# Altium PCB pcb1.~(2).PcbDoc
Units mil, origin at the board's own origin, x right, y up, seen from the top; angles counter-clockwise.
Board outline 3620 x 2165 mil, 2 copper layers (Top Layer, Bottom Layer); 65 components, 116 nets, 447 pads, 112 vias.
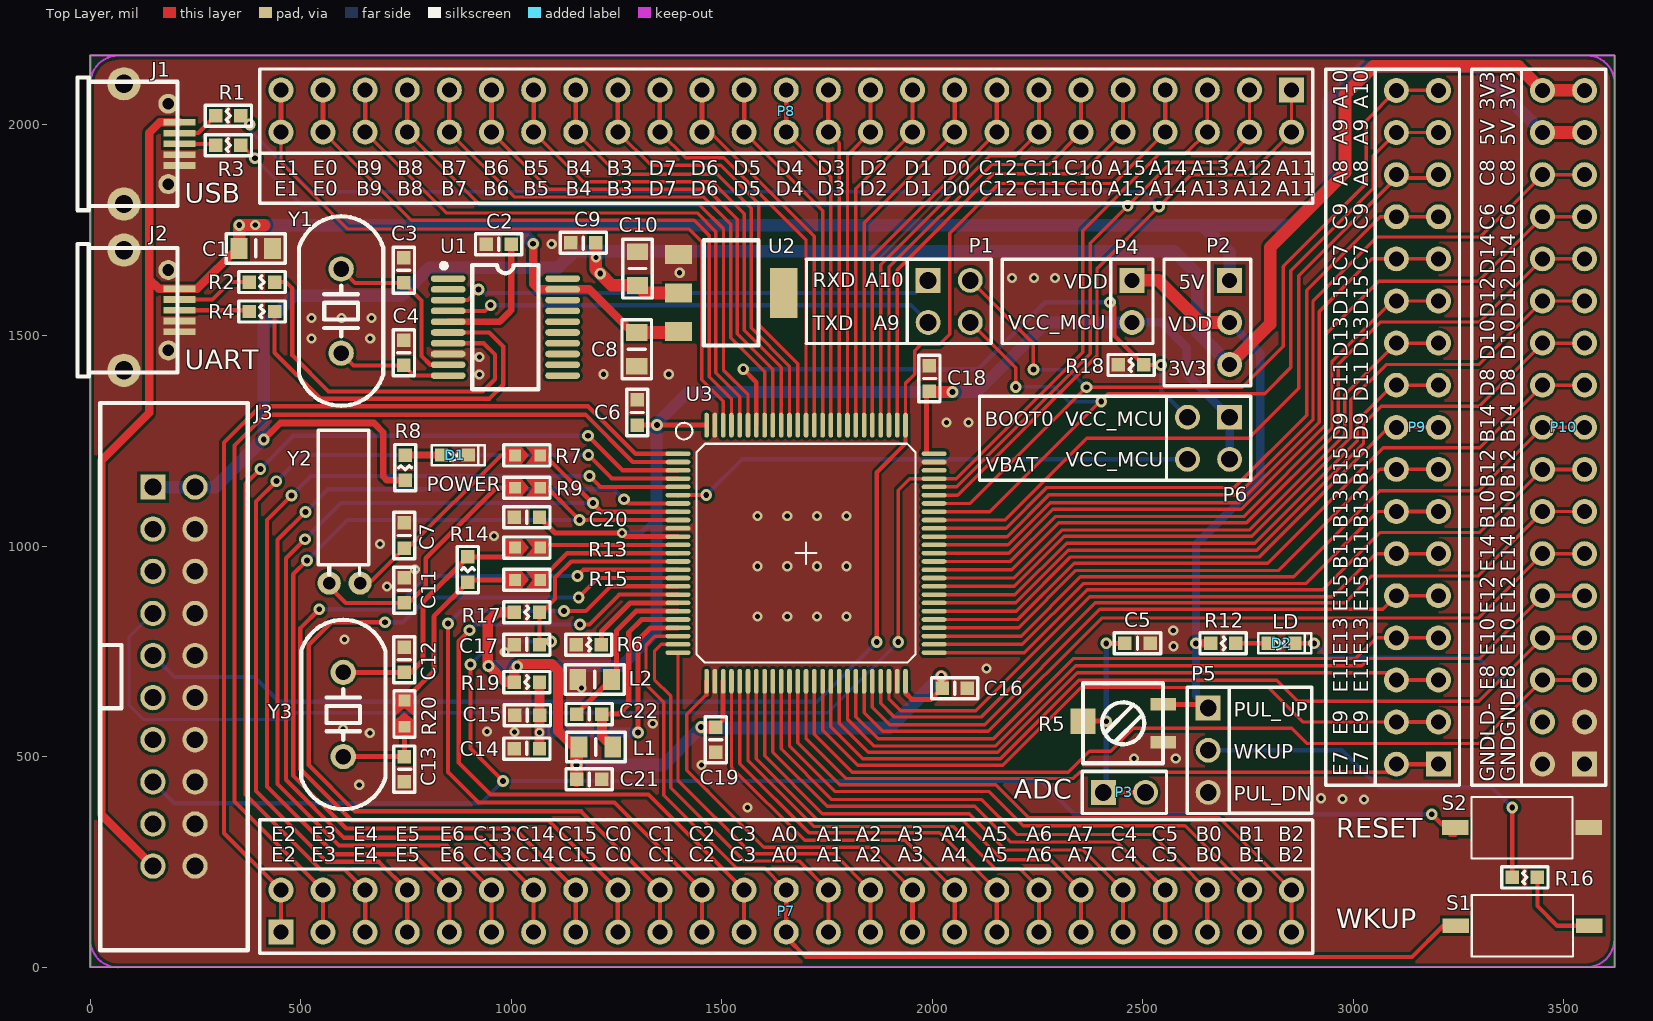
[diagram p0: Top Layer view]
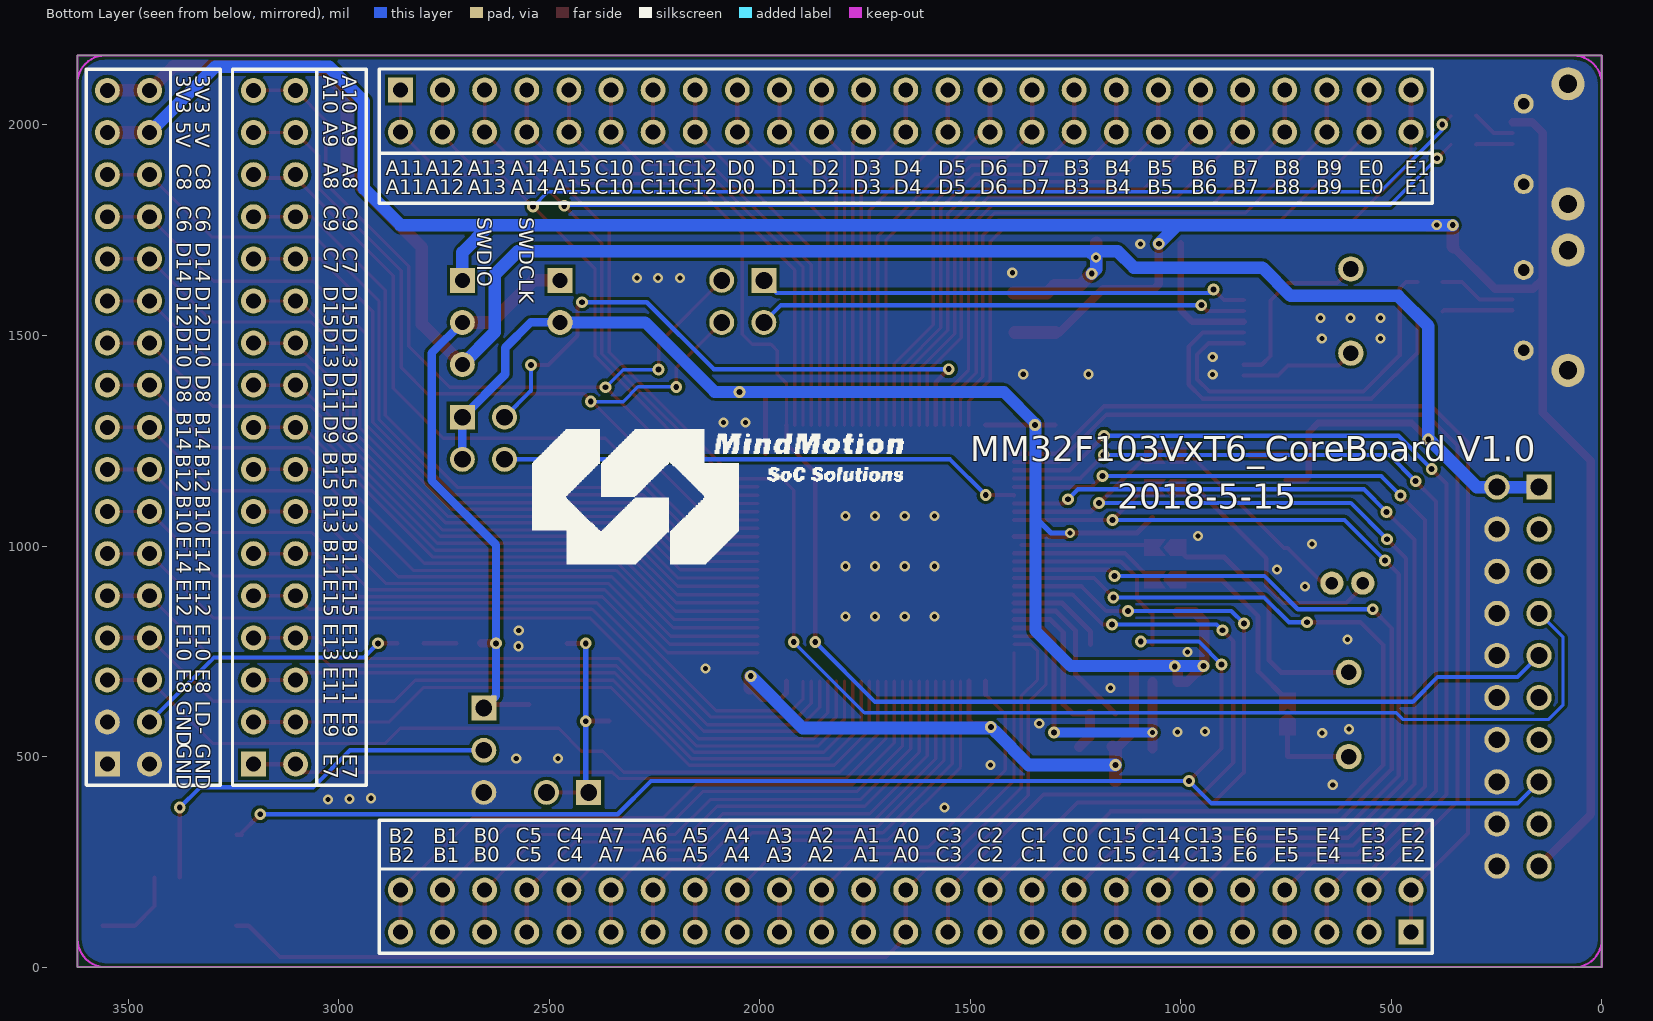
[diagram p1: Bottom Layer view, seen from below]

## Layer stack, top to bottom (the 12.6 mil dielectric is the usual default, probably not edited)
Top Layer: signal copper 1.4
Dielectric: dielectric 12.6, FR-4, Dk 4.8
Bottom Layer: signal copper 1.4

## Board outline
0,0 0,2165 3620,2165 3620,0

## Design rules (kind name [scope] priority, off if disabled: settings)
Clearance [All] p1: gap=7
MinimumSolderMaskSliver [All] p1: minsoldermaskwidth=8
PolygonConnect [All] p1: connectstyle=Direct reliefconductorwidth=10 reliefentries=4 polygonreliefangle="90 Angle"
RoutingVias [All] p1: holewidth=28 width=50 viastyle="Through Hole" minholewidth=14 minwidth=28 maxholewidth=30 maxwidth=50
SilkToSilkClearance [All] p1: silktosilkclearance=0
SilkscreenOverComponentPads [All] p1: minsilkscreentomaskgap=8
SolderMaskExpansion [All] p1: expansion=4
Width [All] p1: maxlimit=50 minlimit=8 preferedwidth=10
25 further rules are at their usual default settings.

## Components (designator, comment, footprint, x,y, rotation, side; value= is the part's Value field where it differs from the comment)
C1 "4.7uF" C-0805 393,1707 r180 top
C2 "104" C-0603 970,1717 r0 top
C3 "22pF" C-0603 745,1655 r270 top
C4 "22pF" C-0603 745,1459 r270 top
C5 "104" C-0603 2487.23,769 r180 top
C6 "104" C-0603 1299,1317 r90 top
C7 "15pF" C-0603 746,1025 r270 top
C8 "4.7uF" C-0805 1298,1467 r90 top
C9 "104" C-0603 1171,1720 r0 top
C10 "10uF" C-0805 1300,1659 r270 top
C11 "15pF" C-0603 746,895 r270 top
C12 "22pF" C-0603 746,730 r270 top
C13 "22pF" C-0603 746,470 r90 top
C14 "1uF" C-0603 1037,519 r180 top
C15 "103" C-0603 1038,598 r180 top
C16 "104" C-0603 2053,662 r180 top
C17 "104" C-0603 1037,765.86 r180 top
C18 "104" C-0603 1993,1398 r90 top
C19 "104" C-0603 1486,540 r270 top
C20 "104" C-0603 1037,1068 r180 top
C21 "1uF" C-0603 1185,446 r0 top
C22 "1uF" C-0603 1185,601 r180 top
D1 "RED" LED-0603 866,1216 r270 top
D2 "BLUE" LED-0603 2829,769 r270 top
J1 "USB_Micro_OX" USB_MICRO_OX_S 206,1955 r90 top
J2 "USB_Micro_OX" USB_MICRO_OX_S 206,1560 r90 top
J3 "CON20A" HEADERBG10X2H 149,1140 r90 top
L1 "Res Semi" C-0805 1201,523 r0 top
L2 "Res Semi" C-0805 1198,682.86 r0 top
P1 "Header 2X2" HDR2X2 1990,1631 r270 top
P2 "Header 3" HDR1X3#1 2706,1631 r270 top
P3 "Header 2" HDR1X2#1 2406,415 r0 top
P4 "Header 2" HDR1X2#2 2474,1631 r270 top
P5 "Header 3" HDR1X3#2 2655,615 r270 top
P6 "Header 2X2" HDR2X2 2706,1305.94 r180 top
P7 "Header 25X2" HDR2X25 453,83 r0 top
P8 "Header 25X2" HDR2X25 2853,2083 r180 top
P9 "Header 17X2" HDR2X17 3202,482 r90 top
P10 "Header 17X2" HDR2X17 3549,482 r90 top
R1 "22R" R-0603 328,2022 r0 top
R2 "22R" R-0603 408,1627 r0 top
R3 "22R" R-0603 328,1952 r0 top
R4 "22R" R-0603 408,1557 r0 top
R5 "10K" R-VR-S 2453,579 r90 top
R6 "0R" R-0603 1184,765.71 r180 top
R7 "NC" NC-0603#1 1009,1216.14 r0 top
R8 "4.7K" R-0603 748,1186 r270 top
R9 "NC" NC-0603#1 1009,1139.29 r0 top
R12 "3K" R-0603 2690.7,769 r180 top
R13 "NC" NC-0603#1 1009,997.43 r0 top
R14 "510K" R-0603 897,944 r270 top
R15 "NC" NC-0603#1 1009,920.57 r0 top
R16 "1K" R-0603 3407,213 r0 top
R17 "47K" R-0603 1037,842.71 r180 top
R18 "4.7K" R-0603 2472,1430 r0 top
R19 "0R" R-0603 1037,677 r180 top
R20 "510R" NC-0603#2 746,575 r90 top
S1 "SW-PB" 3x6x2.5 3281,171 r0 top
S2 "SW-PB" 3x6x2.5 3280,404 r0 top
U1 "CH340T" SSOP-20_208MIL 986,1520 r270 top
U2 "LD1117" SOT223 1522,1601 r270 top
U3 "MM32F103VET6" LQFP100 1700,983 r0 top
Y1 "12M" X'TAL 596,1458 r90 top
Y2 "32.768K" X'TAL-32768 641,912 r180 top
Y3 "8M" X'TAL 601,500 r90 top

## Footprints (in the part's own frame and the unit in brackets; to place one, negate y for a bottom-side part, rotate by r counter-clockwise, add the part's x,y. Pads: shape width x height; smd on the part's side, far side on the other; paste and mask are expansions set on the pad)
3x6x2.5 [mm]
  rect 1.6x0.9 smd: 1(-0.965,-1.85) 2(7.087,-1.85)
  silkscreen extent 0,-3.71 6.1,0
C-0603 [mil]
  rect 32x32 smd: 1(-30,0) 2(30,0)
  silkscreen extent -55,-25 55,25
C-0805 [mil]
  rect 40x50 smd: 1(-40,0) 2(40,0)
  silkscreen extent -70,-35 70,35
HDR1X2#1 [mm] "Connector; Header; 2 Position"
  rect 1.5x1.5 hole 1.016: 1(0,0)
  round 1.5 hole 1.016: 2(2.54,0)
  silkscreen extent -1.27,-1.27 3.81,1.27
HDR1X2#2 [mm] "Connector; Header; 2 Position"
  rect 1.5x1.5 hole 0.9: 1(0,0)
  round 1.5 hole 0.9: 2(2.54,0)
  silkscreen extent -1.27,-1.27 3.81,1.27
HDR1X3#1 [mm] "Connector; Header; 3 Position"
  rect 1.5x1.5 hole 0.9: 1(0,0)
  round 1.5 hole 0.9: 2(2.54,0) 3(5.08,0)
  silkscreen extent -1.27,-1.27 6.35,1.27
HDR1X3#2 [mm] "Connector; Header; 3 Position"
  rect 1.5x1.5 hole 1.016: 1(0,0)
  round 1.5 hole 1.016: 2(2.54,0) 3(5.08,0)
  silkscreen extent -1.27,-1.27 6.35,1.27
HDR2X2 [mm] "Connector; Header; 2x2 Position"
  rect 1.5x1.5 hole 1.016: 1(0,0)
  round 1.5 hole 1.016: 2(0,2.54) 3(2.54,0) 4(2.54,2.54)
  silkscreen extent -1.27,-1.27 3.81,3.81
HDR2X17 [mm] "Connector; Header; 17x2 Position"
  rect 1.5x1.5 hole 0.9: 1(0,0)
  round 1.5 hole 0.9: 2(0,2.54) 3(2.54,0) 4(2.54,2.54) 5(5.08,0) 6(5.08,2.54) 7(7.62,0) 8(7.62,2.54) 9(10.16,0) 10(10.16,2.54) 11(12.7,0) 12(12.7,2.54) 13(15.24,0) 14(15.24,2.54) 15(17.78,0) 16(17.78,2.54) 17(20.32,0) 18(20.32,2.54) 19(22.86,0) 20(22.86,2.54) 21(25.4,0) 22(25.4,2.54) 23(27.94,0) 24(27.94,2.54) 25(30.48,0) 26(30.48,2.54) 27(33.02,0) 28(33.02,2.54) 29(35.56,0) 30(35.56,2.54) 31(38.1,0) 32(38.1,2.54) 33(40.64,0) 34(40.64,2.54)
  silkscreen extent -1.27,-1.27 41.91,3.81
HDR2X25 [mm] "Connector; Header; 25x2 Position"
  rect 1.5x1.5 hole 0.9: 1(0,0)
  round 1.5 hole 0.9: 2(0,2.54) 3(2.54,0) 4(2.54,2.54) 5(5.08,0) 6(5.08,2.54) 7(7.62,0) 8(7.62,2.54) 9(10.16,0) 10(10.16,2.54) 11(12.7,0) 12(12.7,2.54) 13(15.24,0) 14(15.24,2.54) 15(17.78,0) 16(17.78,2.54) 17(20.32,0) 18(20.32,2.54) 19(22.86,0) 20(22.86,2.54) 21(25.4,0) 22(25.4,2.54) 23(27.94,0) 24(27.94,2.54) 25(30.48,0) 26(30.48,2.54) 27(33.02,0) 28(33.02,2.54) 29(35.56,0) 30(35.56,2.54) 31(38.1,0) 32(38.1,2.54) 33(40.64,0) 34(40.64,2.54) 35(43.18,0) 36(43.18,2.54) 37(45.72,0) 38(45.72,2.54) 39(48.26,0) 40(48.26,2.54) 41(50.8,0) 42(50.8,2.54) 43(53.34,0) 44(53.34,2.54) 45(55.88,0) 46(55.88,2.54) 47(58.42,0) 48(58.42,2.54) 49(60.96,0) 50(60.96,2.54)
  silkscreen extent -1.27,-1.27 62.23,3.81
HEADERBG10X2H [mil]
  rect 60x60 hole 40: 1(0,0)
  round 60 hole 40: 2(0,-100) 3(-100,0) 4(-100,-100) 5(-200,0) 6(-200,-100) 7(-300,0) 8(-300,-100) 9(-400,0) 10(-400,-100) 11(-500,0) 12(-500,-100) 13(-600,0) 14(-600,-100) 15(-700,0) 16(-700,-100) 17(-800,0) 18(-800,-100) 19(-900,0) 20(-900,-100)
  silkscreen extent -1100,-225 200,125
LED-0603 [mm]
  rect 0.8x0.8 smd: 1(0,-0.8) 2(0,0.8)
  silkscreen extent -0.6,-1.4 0.6,1.8
LQFP100 [mm]
  oval 1.5x0.279 smd: 1(-7.725,6) 2(-7.725,5.5) 3(-7.725,5) 4(-7.725,4.5) 5(-7.725,4) 6(-7.725,3.5) 7(-7.725,3) 8(-7.725,2.5) 9(-7.725,2) 10(-7.725,1.5) 11(-7.725,1) 12(-7.725,0.5) 13(-7.725,0) 14(-7.725,-0.5) 15(-7.725,-1) 16(-7.725,-1.5) 17(-7.725,-2) 18(-7.725,-2.5) 19(-7.725,-3) 20(-7.725,-3.5) 21(-7.725,-4) 22(-7.725,-4.5) 23(-7.725,-5) 24(-7.725,-5.5) 25(-7.725,-6) 51(7.725,-6) 52(7.725,-5.5) 53(7.725,-5) 54(7.725,-4.5) 55(7.725,-4) 56(7.725,-3.5) 57(7.725,-3) 58(7.725,-2.5) 59(7.725,-2) 60(7.725,-1.5) 61(7.725,-1) 62(7.725,-0.5) 63(7.725,0) 64(7.725,0.5) 65(7.725,1) 66(7.725,1.5) 67(7.725,2) 68(7.725,2.5) 69(7.725,3) 70(7.725,3.5) 71(7.725,4) 72(7.725,4.5) 73(7.725,5) 74(7.725,5.5) 75(7.725,6)
  oval 0.279x1.5 smd: 26(-6,-7.725) 27(-5.5,-7.725) 28(-5,-7.725) 29(-4.5,-7.725) 30(-4,-7.725) 31(-3.5,-7.725) 32(-3,-7.725) 33(-2.5,-7.725) 34(-2,-7.725) 35(-1.5,-7.725) 36(-1,-7.725) 37(-0.5,-7.725) 38(0,-7.725) 39(0.5,-7.725) 40(1,-7.725) 41(1.5,-7.725) 42(2,-7.725) 43(2.5,-7.725) 44(3,-7.725) 45(3.5,-7.725) 46(4,-7.725) 47(4.5,-7.725) 48(5,-7.725) 49(5.5,-7.725) 50(6,-7.725) 76(6,7.725) 77(5.5,7.725) 78(5,7.725) 79(4.5,7.725) 80(4,7.725) 81(3.5,7.725) 82(3,7.725) 83(2.5,7.725) 84(2,7.725) 85(1.5,7.725) 86(1,7.725) 87(0.5,7.725) 88(0,7.725) 89(-0.5,7.725) 90(-1,7.725) 91(-1.5,7.725) 92(-2,7.725) 93(-2.5,7.725) 94(-3,7.725) 95(-3.5,7.725) 96(-4,7.725) 97(-4.5,7.725) 98(-5,7.725) 99(-5.5,7.725) 100(-6,7.725)
  silkscreen extent -7.86,-6.6 6.6,7.87
NC-0603#1 [mil]
  rect 28x28 smd: 1(0,-1) 2(60,-1)
  Top Layer region: -22,-21 16,-21 32,-1 16,19 -22,19
  Top Layer region: 26,19 42,-1 26,-21 78,-21 78,19
  silkscreen extent -27,-26 83,24
NC-0603#2 [mil]
  rect 28x28 smd: 1(-4,-0.33) 2(58,-0.33)
  Top Layer region: -24,-20.33 14,-20.33 30,-0.33 14,19.67 -24,19.67
  Top Layer region: 24,19.67 40,-0.33 24,-20.33 76,-20.33 76,19.67
  silkscreen extent -29,-25 81,25
R-0603 [mil]
  rect 32x32 smd: 1(-30,0) 2(30,0)
  silkscreen extent -55,-25 55,25
R-VR-S [mil]
  rect 30x60 smd: 1(-45,-95) 3(45,-95)
  rect 60x60 smd: 2(5,95)
  silkscreen extent -95,-95 95,95
SOT223 [mil]
  rect 45x65 smd: 1(-91,-125) 2(0,-125) 3(91,-125)
  rect 118x65 smd: 4(0,125)
  silkscreen extent -125,-65 125,65
SSOP-20_208MIL [mm]
  oval 0.4x2.1 smd mask+0.051: 1(-2.925,-3.45) 2(-2.275,-3.45) 3(-1.625,-3.45) 4(-0.975,-3.45) 5(-0.325,-3.45) 6(0.325,-3.45) 7(0.975,-3.45) 8(1.625,-3.45) 9(2.275,-3.45) 10(2.925,-3.45) 11(2.925,3.45) 12(2.275,3.45) 13(1.625,3.45) 14(0.975,3.45) 15(0.325,3.45) 16(-0.325,3.45) 17(-0.975,3.45) 18(-1.625,3.45) 19(-2.275,3.45) 20(-2.925,3.45)
  silkscreen extent -3.85,-3.86 3.75,2
USB_MICRO_OX_S [mm]
  rect 0.4x1.905 smd: 1(1.3,-0.153) 2(0.65,-0.153) 3(0,-0.153) 4(-0.65,-0.153) 5(-1.3,-0.153)
  round 1.2 hole 0.7: 6(2.425,0.52) 7(-2.425,0.52)
  round 2 hole 1.1: 8(-3.625,3.2) 9(3.625,3.2)
  silkscreen extent -4,-0.04 4,6
X'TAL [mil]
  round 60 hole 37: 1(0,0) 2(200,0)
  silkscreen extent -125,-100 325,100
X'TAL-32768 [mil]
  round 55 hole 30: 1(73.35,0) 2(0,0)
  silkscreen extent -21,-363 99,-20

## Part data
C1 C2 C3 C4 C5 C6 C7 C8 C9 C10 C11 C12 C13 C14 C15 C16 C18 C19 C20 C21 C22: library part CAP, "Capacitor"
C17: library part Cap, "Capacitor"
D1 D2: library part LED0, "Typical INFRARED GaAs LED"
L1 L2: "Semiconductor Resistor"
P1 P6: "Header, 2-Pin, Dual row"
P2 P5: "Header, 3-Pin"
P3 P4: "Header, 2-Pin"
P7 P8: "Header, 25-Pin, Dual row"
P9 P10: "Header, 17-Pin, Dual row"
R1 R2 R3 R4 R6 R7 R8 R9 R12 R13 R15 R16 R17 R18 R19 R20: library part Res2, "Resistor"
R5: library part "RESISTOR VAR"
R14: library part RES
S1 S2: "Switch"
U2: library part LD1117/SOT_0
U3: library part LQFP100
Y1 Y2 Y3: library part XTAL, "Crystal Oscillator"

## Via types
v1: diameter 28, hole 14, Top Layer to Bottom Layer, 57 vias
v2: diameter 24, hole 12, Top Layer to Bottom Layer, 55 vias

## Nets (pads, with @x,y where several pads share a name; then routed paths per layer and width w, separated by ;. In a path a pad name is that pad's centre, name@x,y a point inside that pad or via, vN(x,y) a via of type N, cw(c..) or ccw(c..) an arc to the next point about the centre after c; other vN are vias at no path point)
3V3: C9.2 C10.2 J3.1 J3.2 P2.3 P10.33 P10.34 R8.2 U2.2 | length 5330.4
  Top Layer w16: v1(412.19,1252.81) 451.37,1292 674,1292 696,1270 696,1165 705,1156 R8.2
  Top Layer w30: v2@1201,1683 1201,1657 v1(1211.24,1646.76) 1239,1619 C10.2 1318,1601 U2.2 ; v2(1201,1685) C9.2 ; P2.3 2802,1527 2802,1709 2980,1887 2980,2072 3047,2139 3392,2139 P10.34 P10.33
  Bottom Layer w30: J3.1 J3.2 297,1140 v1@409.81,1252.81 ; v1(1211.24,1646.76) 1201,1657 v2(1201,1685) 1216,1700 ; P2.3 2629,1508 2629,1645 2574,1700 1216,1700 ; v1@409.81,1252.81 v1@412.19,1255.19 ; v1@409.81,1252.81 v1(412.19,1252.81) v1@412.19,1255.19 ; v1@412.19,1255.19 412.19,1522.19 484,1594 739,1594 806,1661 1111,1661 1150,1700 1216,1700
+5V: C1.2 C8.2 J1.1 J2.1 J3.19 P2.1 P10.31 P10.32 U1.19 U2.3 | length 6551.2
  Top Layer w20: J3.19 26,363 26,1202 140,1316 140,1634 ; J1.1 165,2006.18 140,1981.18 140,1646 140,1634 ; C1.2@353,1710 254.18,1611.18 J2.1 162.82,1611.18 140,1634 ; v1(1052,1718) 1052,1622 1064.43,1609.57 U1.19 1185.43,1609.57 1288,1507 C8.2 ; U2.3@1394,1507 U2.3
  Top Layer w30: C1.2@353,1710 354,1711 v1(354,1762) v2(392,1762) 413,1762 ; C8.2 U2.3@1394,1507 ; P10.32 P10.31
  Bottom Layer w30: v1(354,1762) v2(392,1762) 983,1762 1008,1762 ; 1016,1762 1008,1762 ; v1(1052,1718) 1008,1762 ; P2.1 2706,1697 2641,1762 ; P10.32 3293,2138 3022,2138 2940,2056 2940,1849 2853,1762 2641,1762 ; 1008,1762 2616,1762 2641,1762
BOOT0: P6.3 R18.2 U3.94 | length 1455.8
  Top Layer w10: v1(1551,1420) 1581.89,1389.11 U3.94 ; v1(2422,1579) 2432.47,1568.53 2432.47,1499.53 R18.2 v1(2543,1430)
  Bottom Layer w10: v1(1551,1420) 2109,1420 2268,1579 v1(2422,1579) ; v1(2543,1430) 2543,1368.94 P6.3
CH340_DN: R2.2 U1.7 | length 916.7
  Top Layer w10: R2.2 465,1627 480,1612 480,1453 566,1367 932,1367 961,1396 961,1455 934.39,1481.61 U1.7
CH340_DP: R4.2 U1.6 | length 935.4
  Top Layer w10: R4.2 438,1459 547,1350 948,1350 981,1383 981,1474 947.8,1507.2 U1.6
GND: C1.1 C2.1 C3.1 C4.1 C5.1 C6.2 C7.1 C8.1 C9.1 C10.1 C11.1 C12.1 C13.1 C14.2 C15.2 C16.1 C17.2 C18.2 C19.2 C20.2 C21.2 D1.2 J1.4 J1.5 J1.6 J1.7 J1.8 J1.9 J2.4 J2.5 J2.6 J2.7 J2.8 J2.9 J3.4 J3.6 J3.8 J3.10 J3.12 J3.14 J3.16 J3.18 J3.20 L2.1 P5.3 P10.1 P10.2 P10.3 R5.1 R6.2 R18.1 S2.2 U1.8 U2.1 U3.10 U3.27 U3.49 U3.74 U3.99
  other v2: 1561,379 3025,398 2974,399 2923,401 639,433 1452,480 2479,495 2578,495 664,556 1008,558 942,560 600,565 1336,579 1167,663 2129,709 984,748 2573,762 604,778 2572,799 1585,833 1655.33,833 1725.67,833 1796,833 705,904 771,944 1585,952 1655.33,952 1725.67,952 1796,952 688,1005 959,1024 1585,1071 1655.33,1071 1725.67,1071 1796,1071 2034,1293 2086,1293 924,1407 1219,1408 1374,1408 924,1449 526,1493 665,1493 526,1542 597,1542 668,1542 2189,1637 2241,1637 2291,1637 1400,1649 1096,1717
LD-: D2.2 P10.4 | length 666
  Top Layer w10: D2.2 v1(2906,769)
  Bottom Layer w10: v1(2906,769) 2940,735 3296,735 P10.4
NetC3_2: C3.2 U1.9 Y1.2 | length 425.8
  Top Layer w10: Y1.2 629,1625 C3.2 787,1583 787,1451 807.57,1430.43 U1.9
NetC4_2: C4.2 U1.10 Y1.1 | length 276.2
  Top Layer w10: Y1.1 625,1429 C4.2 769.16,1404.84 U1.10
NetC5_2: C5.2 P3.1 P3.2 R5.2 | length 546.2
  Top Layer w10: P3.1 P3.2
  Top Layer w12: R5.2 v1(2413,584) ; v1(2413,769) C5.2
  Bottom Layer w12: P3.1@2413,422 v1(2413,769)
NetC7_2: C7.2 R7.1 Y2.2 | length 520.4
  Top Layer w10: Y2.2 663,912 C7.2 755,995 975.14,1215.14 R7.1 982.14,1215.14
NetC11_2: C11.2 R9.1 Y2.1 | length 630.2
  Top Layer w10: Y2.1@567.65,891.35 Y2.1 ; Y2.1@567.65,904.35 607,865 C11.2 757,865 797,905 797,971 964.29,1138.29 R9.1
NetC12_2: C12.2 R13.1 R14.1 Y3.2 | length 612.2
  Top Layer w12: Y3.2 C12.2 762,700 790,728 790,867 R14.1 986.57,974 R13.1
NetC13_2: C13.2 R20.1 Y3.1 | length 216.1
  Top Layer w12: Y3.1 C13.2 746,570.67 R20.1
NetC14_1: C14.1 C15.1 R19.1 U3.22 | length 718.2
  Top Layer w12: v1(1301,557) 1301,776 1330.83,805.83 U3.22
  Top Layer w24: C14.1 R19.1
  Bottom Layer w24: v2(1067,557) v1(1301,557)
NetD1_1: D1.1 R8.1 | length 86.5
  Top Layer w16: R8.1 D1.1
NetD2_1: D2.1 R12.1 | length 76.8
  Top Layer w10: R12.1 D2.1
NetJ2_2: J2.2 R2.1 | length 183.1
  Top Layer w10: J2.2 290.59,1585.59 332,1627 R2.1
NetJ2_3: J2.3 R4.1 | length 167.2
  Top Layer w10: J2.3 375,1560 R4.1
NetP1_1: P1.1 U1.3 | length 1165.9
  Top Layer w10: U1.3 896.98,1583.98 v1(922,1609)
  Bottom Layer w10: v1(922,1609) 930,1601 1960,1601 P1.1
NetP1_3: P1.3 U1.4 | length 1162.4
  Top Layer w10: U1.4 937.39,1558.39 v1(951,1572)
  Bottom Layer w10: v1(951,1572) 1949,1572 P1.3
NetP5_2: P5.2 R16.1 | length 944.3
  Top Layer w10: R16.1 v1(3377,379)
  Bottom Layer w10: P5.2 2973,515 3061,427 3329,427 v1(3377,379)
NetR6_1: R6.1 U3.19 | length 240.3
  Top Layer w12: R6.1@1214,766.71 1214,797 1281.89,864.89 U3.19
NetR13_2: R13.2 U3.12 | length 311.5
  Top Layer w10: R13.2 1075.26,1002.68 U3.12@1377.87,1002.68
NetR14_2: R14.2 R15.1 R20.2 | length 457.7
  Top Layer w12: R20.2 816,702.67 816,833 R14.2 902.57,919.57 R15.1
NetR15_2: R15.2 U3.13 | length 353.1
  Top Layer w10: R15.2 1132.43,983 U3.13
NetR16_2: R16.2 S1.2 | length 210.4
  Top Layer w10: R16.2 3437,145 3483.83,98.17 S1.2
NRST: C17.1 J3.15 R17.1 S2.1 U3.14 | length 4234.5
  Top Layer w10: v1(903,719) 903,519 v1(980,442) ; v1(1095,773) 1074.14,773 C17.1 R17.1 1072.71,842.71 1104,874 1104,925 1142.32,963.32 U3.14 ; v1(3186,363) S2.1@3234.83,314.17 ; S2.1@3229.17,314.17 S2.1@3234.83,314.17 ; S2.1@3242,314.17 S2.1@3234.83,314.17
  Bottom Layer w10: J3.15 200,389 927,389 v1(980,442) 2258,442 2337,363 v1(3186,363) ; v1(903,719) 957,773 v1(1095,773)
PA0: P7.25 P7.26 S1.1 U3.23 | length 2595.4
  Top Layer w8: U3.23 1341.15,786.15 1320,765 1320,671 1362,629 1362,408 1534.5,235.5 1600.5,235.5 P7.26@1647.38,188.62
  Top Layer w10: P7.26@1647.38,188.62 P7.26 P7.25 1653,71 1700,24 3139,24 3213.17,98.17 S1.1
PA1: P7.27 P7.28 U3.24 | length 977.5
  Top Layer w8: U3.24 1356.47,766.47 1340,750 1340,683 1379,644 1379,426 1553,252 1684,252 P7.28
  Top Layer w10: P7.27 P7.28
PA2: P7.29 P7.30 U3.25 | length 967.9
  Top Layer w8: U3.25 1395.87,444.13 1571,269 1767,269 P7.30
  Top Layer w10: P7.29 P7.30
PA3: P7.31 P7.32 U3.26 | length 999
  Top Layer w8: 1463.78,421.22 1474.21,410.79 ; 1463.78,647.78 1417,601 1417,468 1474.21,410.79 ; P7.32 1851,285 1600,285 1474.21,410.79
  Top Layer w12: 1463.78,647.78 U3.26 ; P7.31 P7.32
PA4: P7.33 P7.34 U3.29 | length 954.9
  Top Layer w8: U3.29 1522.83,475.17 1697,301 1935,301 P7.34
  Top Layer w10: P7.33 P7.34
PA5: P7.35 P7.36 U3.30 | length 1030.3
  Top Layer w8: U3.30 1542.52,483.48 1707,319 1894,319 2017,319 P7.36
  Top Layer w10: P7.35 P7.36
PA6: P7.37 P7.38 U3.31 | length 1109.9
  Top Layer w8: U3.31 1562.2,489.79 1717.99,334 2049,334 2149,234 2207,234 P7.38@2253,188
  Top Layer w10: P7.37 2253,176 P7.38 P7.38@2253,188
PA7: P7.39 P7.40 U3.32 | length 1184.1
  Top Layer w8: U3.32 1581.89,495.11 1728,349 2072,349 2166,255 2281,255 P7.40
  Top Layer w10: P7.39 P7.40
PA8: P9.29 P9.30 U3.67 | length 1694
  Top Layer w8: U3.67 2172.11,1061.74 2366.37,1256 2751,1256 2870,1375 2870,1642 P9.30@3102,1874
  Top Layer w10: P9.30@3102,1874 3194,1874 P9.29
PA9: P1.4 P9.31 P9.32 U3.68 | length 2166
  Top Layer w8: U3.68 2136.43,1081.43 2417,1362 2789,1362 2851,1424 2851,1654 3047,1850 3047,1927 P9.32 P9.31 ; P1.4 2198,1423 v1(2198,1378)
  Bottom Layer w8: v1(2198,1378) 2289,1378 2324,1343 v1(2401,1343)
PA10: P1.2 P9.33 P9.34 U3.69 | length 2220.3
  Top Layer w8: U3.69 2090.11,1101.11 v1(2366,1377) 2736,1377 2833,1474 2833,1664 3030,1861 3030,2010 P9.34 P9.33 ; P1.2 2240,1481 v1(2240,1419)
  Bottom Layer w8: v1(2240,1419) 2324,1419 v1(2366,1377)
PA11: P8.1 P8.2 R1.2 U3.70 | length 3691.3
  Top Layer w8: R1.2 v1(379,2001) ; U3.70 2059.79,1120.79 2391,1452 2391,1659 v1(2538,1806) 2613,1881 2648,1881 2751,1881 P8.2 P8.1
  Bottom Layer w8: v1@379,1988 526,1841 2503,1841 v1(2538,1806)
PA12: P8.3 P8.4 R3.2 U3.71 | length 3522.5
  Top Layer w8: R3.2@358,1954 v1(391,1921) ; U3.71 2058.27,1140.48 2375,1457.21 2375,1719 v1(2464,1808) 2567.5,1911.5 2690.5,1911.5 2703.56,1924.56 2753,1974 P8.4 P8.3
  Bottom Layer w8: v1(391,1921) 503,1809 v1@2464,1809
PA13: J3.7 P8.5 P8.6 U3.72 | length 3874.4
  Top Layer w8: v1(1919,772) 1919,1133 1946.17,1160.17 U3.72 2056.74,1160.17 2357,1460.43 2357,1668 2357,1749 2539.07,1931.07 2601.07,1931.07 P8.6 P8.5
  Bottom Layer w8: J3.7 92,783 92,623 127,588 472,588 488,604 1751,604 v1(1919,772)
PA14: J3.9 P8.7 P8.8 U3.76 | length 3604.3
  Top Layer w8: U3.76 1936.22,1386.22 1958,1408 1958,1464 1973,1479 2017,1479 2041,1503 2041,1743 2159,1861 2431,1861 P8.8
  Top Layer w10: v1(1868,772) 1868,1175 1936.22,1243.22 U3.76 U3.76@1937,1286.35 ; P8.8 P8.7
  Bottom Layer w10: J3.9 200,689 390,689 449,630 1726,630 v1(1868,772)
PA15: P8.9 P8.10 U3.77 | length 1140.5
  Top Layer w8: U3.77 1916.53,1395.53 1916.53,1655.53 2145,1884 2354,1884 P8.10
  Top Layer w10: P8.10 P8.9
PB0: P7.45 P7.46 U3.35 | length 1425.4
  Top Layer w8: U3.35 1640.94,518.06 1761,398 2117,398 2200,315 2521,315 2585.74,250.26 ; 2576,260 2585.74,250.26 ; P7.46 2585.74,250.26
  Top Layer w10: P7.45 P7.46
PB1: P7.47 P7.48 U3.36 | length 1507.5
  Top Layer w8: U3.36 1660.63,525.37 1769,417 1995,417 2135,417 2216,336 2600,336 2668,268 ; 2654,282 2668,268 ; P7.48 2668,268
  Top Layer w10: P7.47 P7.48
PB2: P7.49 P7.50 U3.37 | length 1563.7
  Top Layer w8: U3.37 1680.32,532.68 1780,433 2151,433 2229,355 2681,355 2731,305 P7.50
  Top Layer w10: P7.49 P7.50
PB3: P8.33 P8.34 U3.89 | length 1069.5
  Top Layer w8: P8.34 1332,1904 1497,1904 1588,1813 1588,1525 1680.32,1432.68 U3.89
  Top Layer w11: P8.34 P8.33
PB4: P8.35 P8.36 U3.90 | length 1144.4
  Top Layer w8: P8.36 1253,1883 1489,1883 1570,1802 1570,1518 1660.63,1427.37 U3.90
  Top Layer w10: P8.36 P8.35
PB5: P8.37 P8.38 U3.91 | length 1218.7
  Top Layer w8: P8.38 1171,1865 1477,1865 1553,1789 1553,1512 1640.94,1424.06 U3.91
  Top Layer w11: P8.38 P8.37
PB6: P8.39 P8.40 U3.92 | length 1293.5
  Top Layer w8: P8.40 1089,1847 1466,1847 1537,1776 1537,1504 1621.26,1419.74 U3.92
  Top Layer w11: P8.40 P8.39
PB7: P8.41 P8.42 U3.93 | length 1369
  Top Layer w8: P8.42 1007,1829 1456,1829 1521,1764 1521,1495 1601.58,1414.42 U3.93
  Top Layer w11: P8.42 P8.41
PB8: P8.43 P8.44 U3.95 | length 1436.2
  Top Layer w8: P8.44 925,1811 1445.95,1811 1504,1752.95 1504,1417.95 1562.2,1359.75 U3.95
  Top Layer w11: P8.44 P8.43
PB9: P8.45 P8.46 U3.96 | length 1513.6
  Top Layer w8: P8.46 845,1791 1441.2,1791 1486,1746.2 1486,1411.2 1542.52,1354.68 U3.96
  Top Layer w10: P8.46 P8.45
PB10: P10.13 P10.14 U3.47 | length 1939.6
  Top Layer w8: U3.47 1877.17,626.83 1910,594 2097.79,594 2116,594 2387,865 2980,865 3044,929 3296,929 P10.14 P10.13
PB11: P9.11 P9.12 U3.48 | length 1513
  Top Layer w8: U3.48 1896.85,637.15 1925,609 2091,609 2103,609 2374,880 2951,880 3053,982 P9.12 P9.11
PB12: P10.15 P10.16 U3.51 | length 1725.1
  Top Layer w8: U3.51 2218.15,746.78 2367.37,896 2927,896 3063,1032 3299,1032 P10.16
  Top Layer w10: P10.16 P10.15
PB13: P9.13 P9.14 U3.52 | length 1328.6
  Top Layer w8: U3.52 2213.8,766.47 2358.33,911 2887,911 3058,1082 P9.14
  Top Layer w10: P9.14 P9.13
PB14: P10.17 P10.18 U3.53 | length 1750.3
  Top Layer w8: U3.53 2210.85,786.15 2351.7,927 2858,927 3062,1131 3298,1131 P10.18 P10.17
PB15: P9.15 P9.16 U3.54 | length 1353.7
  Top Layer w8: U3.54 2204.83,805.83 2341,942 2823,942 3063,1182 P9.16 P9.15
PC0: P7.17 P7.18 U3.15 | length 2262.2
  Top Layer w10: v1(544,850) 499,805 499,470 620,349 1087,349 P7.18 P7.17 ; v1(1157,929) 1171.63,943.63 U3.15
  Bottom Layer w10: v1(544,850) 722,850 801,929 v1(1157,929)
PC1: P7.19 P7.20 U3.16 | length 2284.7
  Top Layer w10: v1(700,819) 573,819 519,765 519,480 629,370 1166,370 P7.20 P7.19 ; v1(1160,878) 1205.94,923.94 U3.16
  Bottom Layer w10: v1(700,819) 743,819 802,878 v1(1160,878)
PC2: P7.21 P7.22 U3.17 | length 1754.4
  Top Layer w10: v1(850,816) 850,463 922,391 1245,391 P7.22 P7.21 ; v1(1125,846) 1177,846 1235.26,904.26 U3.17
  Bottom Layer w10: v1(850,816) 880,846 v1(1125,846)
PC3: P7.23 P7.24 U3.18 | length 1758.2
  Top Layer w10: v1(901,800) 875,774 875,486 951,410 1326,410 P7.24 P7.23 ; v1(1163,814) 1186,814 1256.58,884.58 U3.18
  Bottom Layer w10: v1(901,800) 915,814 v1(1163,814)
PC4: P7.41 P7.42 U3.33 | length 1260.8
  Top Layer w8: U3.33 1601.58,501.42 1739,364 2088,364 2174,278 2358,278 P7.42
  Top Layer w10: P7.41 P7.42
PC5: P7.43 P7.44 U3.34 | length 1412
  Top Layer w8: U3.34 1621.26,510.74 1750,382 2101,382 2186,297 2439,297 P7.44
  Top Layer w10: 2499,237 P7.44 P7.43
PC6: P10.27 P10.28 U3.63 | length 2001.8
  Top Layer w8: U3.63 2182,983 2286,1087 2733,1087 2934,1288 2934,1503 3060,1629 3296,1629 P10.28 P10.27
PC7: P9.25 P9.26 U3.64 | length 1633.2
  Top Layer w8: U3.64 2179.68,1002.68 2280,1103 2727.79,1103 2919,1294.21 2919,1557 3044,1682 P9.26 P9.25
PC8: P10.29 P10.30 U3.65 | length 2065.5
  Top Layer w8: U3.65 2177.37,1022.37 2277,1122 2725,1122 2904,1301 2904,1582 3056,1734 3301,1734 P10.30 P10.29
PC9: P9.27 P9.28 U3.66 | length 1677.8
  Top Layer w8: U3.66 2175.06,1042.06 2272,1139 2717,1139 2889,1311 2889,1607 3064,1782 P9.28 P9.27
PC10: P8.11 P8.12 U3.78 | length 1063.9
  Top Layer w8: U3.78 1896.85,1400.85 1896.85,1661.85 2141,1906 2276,1906 P8.12
  Top Layer w10: P8.12 P8.11
PC11: P8.13 P8.14 U3.79 | length 987.3
  Top Layer w8: U3.79 1877.17,1410.17 1877.17,1668.17 2136,1927 2197,1927 P8.14
  Top Layer w10: P8.14 P8.13
PC12: P8.15 P8.16 U3.80 | length 918.3
  Top Layer w8: U3.80 1857.48,1419.44 1857.48,1687.48 P8.16
  Top Layer w10: P8.16 P8.15
PC13: P7.11 P7.12 U3.7 | length 2307
  Top Layer w10: v1(511,1081) 445,1015 445,435 591,289 847,289 P7.12 P7.11 ; v1(1268,1111) 1277.89,1101.11 U3.7
  Bottom Layer w10: v1(511,1081) 565,1135 1244,1135 v1(1268,1111)
PC14: P7.13 P7.14 R7.2 U3.8 | length 2503.7
  Top Layer w10: v1(510,1016) 465,971 465,445 603,307 929,307 P7.14 P7.13 ; R7.2 1079.86,1215.14 v1@1193.5,1101.5 ; v1(1194,1102) v1@1193.5,1101.5 ; U3.8 1213.57,1081.43 v1@1193.5,1101.5
  Bottom Layer w10: v1(510,1016) 596,1102 674,1102 ; 659,1102 674,1102 ; v1(1194,1102) 674,1102
PC15: P7.15 P7.16 R9.2 U3.9 | length 2457.8
  Top Layer w10: v1@515,962 v1(515,966) 482,933 482,455 608,329 1007,329 P7.16 P7.15 ; R9.2 1085.71,1138.29 v1(1162.26,1061.74) U3.9
  Bottom Layer w10: v1(515,966) 610.74,1061.74 v1(1162.26,1061.74)
PD0: P8.17 P8.18 U3.81 | length 885
  Top Layer w8: U3.81 1837.8,1423.8 1837.8,1767.8 P8.18
  Top Layer w10: P8.18 P8.17
PD1: P8.19 P8.20 U3.82 | length 851.7
  Top Layer w8: U3.82 1818.11,1431.11 1818.11,1848.11 P8.20
  Top Layer w10: P8.20 P8.19
PD2: P8.21 P8.22 U3.83 | length 818.5
  Top Layer w8: U3.83 1798.43,1440.43 1798.43,1928.43 P8.22
  Top Layer w10: P8.22 P8.21
PD3: P8.23 P8.24 U3.84 | length 806.5
  Top Layer w8: P8.24 1778.74,1957.26 1778.74,1448.74 U3.84
  Top Layer w11: P8.24 P8.23
PD4: P8.25 P8.26 U3.85 | length 839.8
  Top Layer w8: P8.26 1759.05,1876.95 1759.05,1462.05 U3.85
  Top Layer w11: P8.26 P8.25
PD5: P8.27 P8.28 U3.86 | length 873.1
  Top Layer w8: P8.28 1739.37,1796.63 1739.37,1476.37 U3.86
  Top Layer w11: P8.28 P8.27
PD6: P8.29 P8.30 U3.87 | length 917.5
  Top Layer w8: P8.30@1472,1983 1719.68,1735.32 1719.68,1483.68 U3.87
  Top Layer w11: P8.29 P8.30 P8.30@1472,1983
PD7: P8.31 P8.32 U3.88 | length 992.6
  Top Layer w8: P8.32 1414,1922 1504.46,1922 1700,1726.46 1700,1491 U3.88
  Top Layer w11: P8.32 P8.31
PD8: P10.19 P10.20 U3.55 | length 1775.4
  Top Layer w8: U3.55 2203.31,825.52 2336.79,959 2797,959 3071,1233 3300,1233 P10.20 P10.19
PD9: P9.17 P9.18 U3.56 | length 1378.8
  Top Layer w8: U3.56 2199.2,845.2 2328,974 2776,974 3084,1282 P9.18 P9.17
PD10: P10.21 P10.22 U3.57 | length 1827.4
  Top Layer w8: U3.57 2197.68,864.89 2322.79,990 2770,990 3024,1244 3024,1290 3066,1332 3299,1332 P10.22 P10.21
PD11: P9.19 P9.20 U3.58 | length 1431.4
  Top Layer w8: U3.58 2196.15,884.58 2318.57,1007 2765.79,1007 3009,1250.21 3009,1297.21 3093.79,1382 P9.20 P9.19
PD12: P10.23 P10.24 U3.59 | length 1877.7
  Top Layer w8: U3.59 2194.62,904.26 2313.36,1023 2759,1023 2994,1258 2994,1347 3078,1431 3298,1431 P10.24 P10.23
PD13: P9.21 P9.22 U3.60 | length 1484.5
  Top Layer w8: U3.60 2193.09,923.94 2307.15,1038 2752.79,1038 2979,1264.21 2979,1359 P9.22 P9.21
PD14: P10.25 P10.26 U3.61 | length 1943.8
  Top Layer w8: U3.61 2188.63,943.63 2300,1055 2746,1055 2964,1273 2964,1432 3064,1532 3299,1532 P10.26 P10.25
PD15: P9.23 P9.24 U3.62 | length 1547.3
  Top Layer w8: U3.62 2185.32,963.32 2292,1070 2739.79,1070 2949,1279.21 2949,1438.21 3092.79,1582 P9.24 P9.23
PE0: P8.47 P8.48 U3.97 | length 1590.9
  Top Layer w8: P8.48 762.5,1773.5 1433.96,1773.5 1470,1737.46 1470,1402.46 1522.83,1349.62 U3.97
  Top Layer w11: P8.48 P8.47
PE1: P8.49 P8.50 U3.98 | length 1705.9
  Top Layer w8: P8.50 453,1911 611,1753 1422,1753 1452,1723 1452,1395 1503.15,1343.85 U3.98
  Top Layer w11: P8.50 P8.49
PE2: P7.1 P7.2 U3.1 | length 2388.3
  Top Layer w10: P7.1 P7.2 318,318 318,1246 404,1332 1182,1332 1294.78,1219.22 U3.1@1405,1219.22
PE3: P7.3 P7.4 U3.2 | length 2372.7
  Top Layer w10: P7.3 P7.4 497,239 343,393 343,1239 416,1312 1176,1312 1288.47,1199.53 U3.2
PE4: P7.5 P7.6 U3.3 | length 2324.1
  Top Layer w10: v1(404,1183) 369,1148 369,410 547,232 604,232 P7.6 P7.5 ; v1(1182,1262) 1264.15,1179.85 U3.3
  Bottom Layer w10: v1(404,1183) 483,1262 v1(1182,1262)
PE5: P7.7 P7.8 U3.4 | length 2314.9
  Top Layer w10: v1(442,1154) 394,1106 394,418 562,250 686,250 P7.8 P7.7 ; v1(1183,1216) 1238.83,1160.17 U3.4
  Bottom Layer w10: v1(442,1154) 504,1216 v1(1183,1216)
PE6: P7.9 P7.10 U3.5 | length 2297.4
  Top Layer w10: v1(478,1120) 420,1062 420,429 581,268 768,268 P7.10 P7.9 ; v1(1186,1166) 1211.52,1140.48 U3.5
  Bottom Layer w10: v1(478,1120) 524,1166 v1(1186,1166)
PE7: P9.1 P9.2 U3.38 | length 1691.9
  Top Layer w8: U3.38 1700,542 1794,448 2335,448 2350,463 P9.2@3083,463
  Top Layer w10: P9.2@3083,463 P9.2 P9.1
PE8: P10.5 P10.6 U3.39 | length 2112.8
  Top Layer w8: U3.39 1719.68,553.32 1810,463 2323,463 2373.08,513.08 2423.08,513.08 2477,567 2854,567 2890,531 3298,531 P10.6
  Top Layer w10: P10.6 P10.5
PE9: P9.3 P9.4 U3.40 | length 1724.1
  Top Layer w8: U3.40 1739.37,562.63 1823,479 2167,479 2352,664 2799,664 2881,582 P9.4
  Top Layer w10: P9.4 P9.3
PE10: P10.7 P10.8 U3.41 | length 2089.6
  Top Layer w8: U3.41 1759.05,570.95 1835,495 2161.79,495 2347.79,681 2818,681 2868,631 3298,631 P10.8
  Top Layer w10: P10.8 P10.7
PE11: P9.5 P9.6 U3.42 | length 1636.9
  Top Layer w8: U3.42 1778.74,579.26 1848,510 2155.57,510 2344.57,699 P9.6@3085,699
  Top Layer w10: P9.6@3085,699 P9.6 P9.5
PE12: P10.9 P10.10 U3.43 | length 2015.1
  Top Layer w8: U3.43 1798.43,588.57 1862,525 2149.36,525 2340.36,716 3020,716 3037,733 3300,733 P10.10
  Top Layer w10: P10.10 P10.9
PE13: P9.7 P9.8 U3.44 | length 1589.2
  Top Layer w8: U3.44 1818.11,594.89 1871,542 2145.15,542 2336.15,733 3006,733 3055,782 P9.8 P9.7
PE14: P10.11 P10.12 U3.45 | length 1979
  Top Layer w8: U3.45 1837.8,604.2 1882,560 2107,560 2133,560 2402,829 3009,829 3296,829 P10.12 P10.11
PE15: P9.9 P9.10 U3.46 | length 1549.8
  Top Layer w8: U3.46 1857.48,617.52 1899,576 2101,576 2124,576 2398,850 3070,850 P9.10 P9.9
USB_DN: J1.2 R1.1 | length 103.1
  Top Layer w10: J1.2 256.59,1980.59 R1.1
USB_DP: J1.3 R3.1 | length 86.4
  Top Layer w10: J1.3 297,1955 R3.1@298,1954
VBAT: P6.4 U3.6 | length 1245.4
  Top Layer w10: U3.6 1396.07,1121 v1(1463,1121)
  Bottom Layer w10: v1(1463,1121) 1547.94,1205.94 P6.4
VCC_MCU: C6.1 C16.2 C18.1 C19.1 C20.1 C21.1 L1.1 P4.2 P6.1 P6.2 R17.2 R19.2 U3.11 U3.28 U3.50 U3.75 U3.100 | length 5391.2
  Top Layer w11: C6.1 C6.1@1299.13,1287.13 ; U3.75@1986.13,1219.22 1986.13,1361.13 C18.1
  Top Layer w12: C20.1 1104,1031 v2(1263,1031) 1271.63,1022.37 U3.11 ; C6.1@1299.13,1287.13 v1(1346,1287.13) U3.100 ; C19.1 1503.15,587.15 U3.28 ; U3.50 1936.22,650.78 1951,636 1997,636 C16.2
  Top Layer w24: R17.2 966.71,842.71 944,820 944,718 985,677 R19.2 1007,707 v1(1014.28,714.28) 1020,720 1096,720 1111,705 1111,561 L1.1@1155,517 ; C18.1 C18.1@1995,1366
  Top Layer w28: C18.1@1995,1366 v1(2048,1366)
  Top Layer w30: C21.1@1155,443 C21.1 v1(1155,480) 1155,517 L1.1 ; v1(1451,570) C19.1 ; v1(2021,691) 2023,689 C16.2
  Bottom Layer w12: v2(1263,1031) 1308,1031 1345,1068
  Bottom Layer w20: P4.2 2544,1531 2604,1471 2604,1407.94 P6.1 P6.2
  Bottom Layer w28: v1(946,715) 1261,715 1345,799 1345,1068 1345,1291 1420,1366 v1(2048,1366) 2107,1366 2272,1531 P4.2
  Bottom Layer w30: v1(1155,480) 1361,480 1439,558 v1@1449,568 ; v1(1451,570) v1@1449,568 ; v1(2021,691) 1898,568 v1@1449,568
VCC_UART: C2.2 U1.5 | length 320.1
  Top Layer w16: U1.5 950,1532.8 972.8,1532.8 995,1555 1000,1560 C2.2@1000,1719
VDD: P2.2 P4.1 P5.1 R5.3 R12.2 | length 1440.5
  Top Layer w12: R5.3 2646,624 P5.1
  Top Layer w20: v1(2626,769) R12.2
  Top Layer w30: P4.1 2537,1631 2637,1531 P2.2
  Bottom Layer w20: P5.1 2626,644 v1(2626,769) 2626,1003 2779,1156 2779,1458 P2.2
VREF+: C22.1 L1.2 U3.21 | length 462.8
  Top Layer w12: C22.1 1256,601 1279,624 1279,795 1309.52,825.52 U3.21
  Top Layer w24: C22.1 1215,549 L1.2
VREF-: C22.2 L2.2 U3.20 | length 403
  Top Layer w12: C22.2 1236.86,682.86 L2.2 1250,694.86 1250,799 1296.2,845.2 U3.20
pads on no net: J3.3 J3.5 J3.11 J3.13 J3.17 U1.1 U1.2 U1.11 U1.12 U1.13 U1.14 U1.15 U1.16 U1.17 U1.18 U1.20 U2.4 U3.73

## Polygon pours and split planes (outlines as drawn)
GND on Top Layer "Top Layer-No Net" (solid, pour order 1000): 1315,631 1315,579.1 1314.25,578.35 1327,565.61 1327,551 1327,541 1317,531 1326,522 1326,422.24 1347.24,422.24 1350,425 1351,426 1351,437 1351,627 1347,631 1342,636 1329,636 1320,636 1315,631
GND on Top Layer "Top Layer-No Net" (solid, remove dead copper, pour order 1000): 0,2165 0,0 3620,0 3620,2165
GND on Bottom Layer "Top Layer-No Net" (solid, remove dead copper, pour order 1001): 0,2165 0,0 3620,0 3620,2165

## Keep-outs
Keep-Out Layer:
  lines w5: 0,66 ccw(c66.03,65.55) 66,-0.48 ; 0.52,2098.5 cw(c66.55,2098.48) 67,2164.5 ; 3553,0 ccw(c3553.45,66.03) 3619.48,66 ; 3554,2165 cw(c3553.97,2098.97) 3620,2098.52 ; 0,2165 3620,2165 ; 0,2165 3620,2165 ; 0,2165 0,0 3620,0 3620,2165

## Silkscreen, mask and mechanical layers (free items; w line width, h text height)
Top Overlay:
  lines w8: 403,233 403,349 402,350 2902,350 2903,349 2903,233 ; 403,1933 403,1814 2903,1814 2903,1933 ; 1700,1481 1940,1481 ; 1700,1681 1940,1681 ; 1701,1481 1701,1681 ; 2424,1481 2166,1481 2166,1681 2424,1681 ; 2562,1156 2112,1156 2112,1356 2562,1356 ; 2656,1381 2550,1381 2550,1681 2656,1681 ; 2706,365 2901,365 2901,665 2706,665 ; 3052,432 2934,432 2934,2132 3052,2132 ; 3399,432 3281,432 3281,2132 3405,2132
  text "A10" at 2986,2039 h35 r90
  text "A10" at 3035,2039 h35 r90
  text "3V3" at 3335,2035 h35 r90
  text "3V3" at 3384,2035 h35 r90
  text "A9" at 2986,1952 h35 r90
  text "A9" at 3035,1952 h35 r90
  text "5V" at 3335,1951 h35 r90
  text "5V" at 3384,1951 h35 r90
  text "E1" at 437,1881 h35
  text "E0" at 529,1881 h35
  text "B9" at 632,1881 h35
  text "B8" at 729,1881 h35
  text "B7" at 834,1881 h35
  text "B6" at 934,1881 h35
  text "B5" at 1029,1881 h35
  text "B4" at 1129,1881 h35
  text "B3" at 1227,1881 h35
  text "D7" at 1326,1881 h35
  text "D6" at 1426,1881 h35
  text "D5" at 1527,1881 h35
  text "D4" at 1628,1881 h35
  text "D3" at 1727,1881 h35
  text "D2" at 1827,1881 h35
  text "D1" at 1933,1881 h35
  text "D0" at 2024,1881 h35
  text "C12" at 2110,1881 h35
  text "C11" at 2216,1881 h35
  text "C10" at 2313,1881 h35
  text "A15" at 2416,1881 h35
  text "A14" at 2514,1881 h35
  text "A13" at 2614,1881 h35
  text "A12" at 2716,1881 h35
  text "A11" at 2817,1881 h35
  text "A8" at 2986,1855 h35 r90
  text "A8" at 3035,1855 h35 r90
  text "C8" at 3335,1854 h35 r90
  text "C8" at 3384,1854 h35 r90
  text "E1" at 437,1832 h35
  text "E0" at 529,1832 h35
  text "B9" at 632,1832 h35
  text "B8" at 729,1832 h35
  text "B7" at 834,1832 h35
  text "B6" at 934,1832 h35
  text "B5" at 1029,1832 h35
  text "B4" at 1129,1832 h35
  text "B3" at 1227,1832 h35
  text "D7" at 1326,1832 h35
  text "D6" at 1426,1832 h35
  text "D5" at 1527,1832 h35
  text "D4" at 1628,1832 h35
  text "D3" at 1727,1832 h35
  text "D2" at 1827,1832 h35
  text "D1" at 1933,1832 h35
  text "D0" at 2024,1832 h35
  text "C12" at 2110,1832 h35
  text "C11" at 2216,1832 h35
  text "C10" at 2313,1832 h35
  text "A15" at 2416,1832 h35
  text "A14" at 2514,1832 h35
  text "A13" at 2614,1832 h35
  text "A12" at 2716,1832 h35
  text "A11" at 2817,1832 h35
  text "USB" at 225,1800 h80
  text "C9" at 2986,1751 h35 r90
  text "C9" at 3035,1751 h35 r90
  text "C6" at 3335,1750 h35 r90
  text "C6" at 3384,1750 h35 r90
  text "C7" at 2986,1654 h35 r90
  text "C7" at 3035,1654 h35 r90
  text "D14" at 3335,1645 h35 r90
  text "D14" at 3384,1645 h35 r90
  text "A10" at 1841,1615 h35
  text "RXD" at 1716,1614 h35
  text "VDD" at 2312,1611 h35
  text "5V" at 2585,1610 h35
  text "D15" at 2986,1548 h35 r90
  text "D15" at 3035,1548 h35 r90
  text "D12" at 3335,1542 h35 r90
  text "D12" at 3384,1542 h35 r90
  text "VCC_MCU" at 2180,1514 h35
  text "A9" at 1861,1513 h35
  text "TXD" at 1716,1512 h35
  text "VDD" at 2560,1510 h35
  text "D13" at 2986,1448 h35 r90
  text "D13" at 3035,1448 h35 r90
  text "D10" at 3335,1441 h35 r90
  text "D10" at 3384,1441 h35 r90
  text "UART" at 225,1405 h80
  text "3V3" at 2560,1405 h35
  text "D8" at 3335,1354 h35 r90
  text "D8" at 3384,1354 h35 r90
  text "D11" at 2986,1343 h35 r90
  text "D11" at 3035,1343 h35 r90
  text "BOOT0" at 2124,1285 h35
  text "VCC_MCU" at 2315,1285 h35
  text "D9" at 2986,1250 h35 r90
  text "D9" at 3035,1250 h35 r90
  text "B14" at 3335,1245 h35 r90
  text "B14" at 3384,1245 h35 r90
  text "VCC_MCU" at 2317,1188 h35
  text "VBAT" at 2127,1176.34 h35
  text "B15" at 2986,1143 h35 r90
  text "B15" at 3035,1143 h35 r90
  text "B12" at 3335,1139 h35 r90
  text "B12" at 3384,1139 h35 r90
  text "POWER" at 799,1130 h35
  text "B13" at 2986,1042 h35 r90
  text "B13" at 3035,1042 h35 r90
  text "B10" at 3335,1041 h35 r90
  text "B10" at 3384,1041 h35 r90
  text "B11" at 2986,945 h35 r90
  text "B11" at 3035,945 h35 r90
  text "E14" at 3335,939 h35 r90
  text "E14" at 3384,939 h35 r90
  text "E15" at 2986,844 h35 r90
  text "E15" at 3035,844 h35 r90
  text "E12" at 3335,839 h35 r90
  text "E12" at 3384,839 h35 r90
  text "LD" at 2807,803 h35
  text "E13" at 2986,741 h35 r90
  text "E13" at 3035,741 h35 r90
  text "E10" at 3335,740 h35 r90
  text "E10" at 3384,740 h35 r90
  text "E8" at 3335,657 h35 r90
  text "E8" at 3384,657 h35 r90
  text "E11" at 2986,651 h35 r90
  text "E11" at 3035,651 h35 r90
  text "PUL_UP" at 2716,595 h35
  text "E9" at 2986,551 h35 r90
  text "E9" at 3035,551 h35 r90
  text "LD-" at 3335,547 h35 r90
  text "GND" at 3384,547 h35 r90
  text "WKUP" at 2716,495 h35
  text "E7" at 2986,453 h35 r90
  text "E7" at 3035,453 h35 r90
  text "GND" at 3335,440 h35 r90
  text "GND" at 3384,440 h35 r90
  text "PUL_DN" at 2716,395 h35
  text "ADC" at 2193,385 h80
  text "E2" at 430,299 h35
  text "E3" at 525,299 h35
  text "E4" at 625,299 h35
  text "E5" at 725,299 h35
  text "E6" at 830,299 h35
  text "C13" at 910,299 h35
  text "C14" at 1011,299 h35
  text "C15" at 1111,299 h35
  text "C0" at 1223,299 h35
  text "C1" at 1325,299 h35
  text "C2" at 1421,299 h35
  text "C3" at 1519,299 h35
  text "A0" at 1619,299 h35
  text "A1" at 1726,299 h35
  text "A2" at 1818,299 h35
  text "A3" at 1918,299 h35
  text "A4" at 2021,299 h35
  text "A5" at 2119,299 h35
  text "A6" at 2223,299 h35
  text "A7" at 2322,299 h35
  text "C4" at 2424,299 h35
  text "C5" at 2521,299 h35
  text "B0" at 2625,299 h35
  text "B1" at 2728,299 h35
  text "B2" at 2822,299 h35
  text "RESET" at 2959,292 h80
  text "E2" at 430,250 h35
  text "E3" at 525,250 h35
  text "E4" at 625,250 h35
  text "E5" at 725,250 h35
  text "E6" at 830,250 h35
  text "C13" at 910,250 h35
  text "C14" at 1011,250 h35
  text "C15" at 1111,250 h35
  text "C0" at 1223,250 h35
  text "C1" at 1325,250 h35
  text "C2" at 1421,250 h35
  text "C3" at 1519,250 h35
  text "A0" at 1619,250 h35
  text "A1" at 1726,250 h35
  text "A2" at 1818,250 h35
  text "A3" at 1918,250 h35
  text "A4" at 2021,250 h35
  text "A5" at 2119,250 h35
  text "A6" at 2223,250 h35
  text "A7" at 2322,250 h35
  text "C4" at 2424,250 h35
  text "C5" at 2521,250 h35
  text "B0" at 2625,250 h35
  text "B1" at 2728,250 h35
  text "B2" at 2822,250 h35
  text "WKUP" at 2959,77 h80
Bottom Overlay:
  drawing of 2012 lines, arcs and shapes, not listed
  text "A10" at 2991,2118 h35 r90
  text "A10" at 3036,2118 h35 r90
  text "3V3" at 3340,2118 h35 r90
  text "3V3" at 3385,2118 h35 r90
  text "A9" at 2991,2009 h35 r90
  text "A9" at 3036,2009 h35 r90
  text "5V" at 3340,2008 h35 r90
  text "5V" at 3385,2008 h35 r90
  text "A8" at 2990,1909 h35 r90
  text "A8" at 3035,1909 h35 r90
  text "C8" at 3339,1908 h35 r90
  text "C8" at 3384,1908 h35 r90
  text "E1" at 468,1881 h35
  text "E0" at 577,1881 h35
  text "B9" at 678,1881 h35
  text "B8" at 778,1881 h35
  text "B7" at 877,1881 h35
  text "B6" at 975,1881 h35
  text "B5" at 1080,1881 h35
  text "B4" at 1180,1881 h35
  text "B3" at 1278,1881 h35
  text "D7" at 1377,1881 h35
  text "D6" at 1477,1881 h35
  text "D5" at 1576,1881 h35
  text "D4" at 1681,1881 h35
  text "D3" at 1778,1881 h35
  text "D2" at 1876,1881 h35
  text "D0" at 2077,1881 h35
  text "C12" at 2193,1881 h35
  text "C11" at 2284,1881 h35
  text "C10" at 2391,1881 h35
  text "A15" at 2490,1881 h35
  text "A14" at 2591,1881 h35
  text "A13" at 2693,1881 h35
  text "D1" at 1973,1880 h35
  text "A12" at 2793,1880 h35
  text "A11" at 2888,1880 h35
  text "E1" at 468,1836 h35
  text "E0" at 577,1836 h35
  text "B9" at 678,1836 h35
  text "B8" at 778,1836 h35
  text "B7" at 877,1836 h35
  text "B6" at 975,1836 h35
  text "B5" at 1080,1836 h35
  text "B4" at 1180,1836 h35
  text "B3" at 1278,1836 h35
  text "D7" at 1377,1836 h35
  text "D6" at 1477,1836 h35
  text "D5" at 1576,1836 h35
  text "D4" at 1681,1836 h35
  text "D3" at 1778,1836 h35
  text "D2" at 1876,1836 h35
  text "D0" at 2077,1836 h35
  text "C12" at 2193,1836 h35
  text "C11" at 2284,1836 h35
  text "C10" at 2391,1836 h35
  text "A15" at 2490,1836 h35
  text "A14" at 2591,1836 h35
  text "A13" at 2693,1836 h35
  text "D1" at 1973,1835 h35
  text "A12" at 2793,1835 h35
  text "A11" at 2888,1835 h35
  text "C9" at 2990,1809 h35 r90
  text "C9" at 3035,1809 h35 r90
  text "C6" at 3339,1808 h35 r90
  text "C6" at 3384,1808 h35 r90
  text "SWDCLK" at 2571,1781 h35 r90
  text "SWDIO" at 2671,1781 h35 r90
  text "D14" at 3339,1721 h35 r90
  text "D14" at 3384,1721 h35 r90
  text "C7" at 2990,1709 h35 r90
  text "C7" at 3035,1709 h35 r90
  text "D15" at 2990,1617 h35 r90
  text "D15" at 3035,1617 h35 r90
  text "D12" at 3339,1617 h35 r90
  text "D12" at 3384,1617 h35 r90
  text "D10" at 3339,1519 h35 r90
  text "D10" at 3384,1519 h35 r90
  text "D13" at 2990,1518 h35 r90
  text "D13" at 3035,1518 h35 r90
  text "D11" at 2990,1413 h35 r90
  text "D11" at 3035,1413 h35 r90
  text "D8" at 3339,1407 h35 r90
  text "D8" at 3384,1407 h35 r90
  text "B14" at 3339,1318 h35 r90
  text "B14" at 3384,1318 h35 r90
  text "D9" at 2990,1309 h35 r90
  text "D9" at 3035,1309 h35 r90
  text "B15" at 2991,1224 h35 r90
  text "B15" at 3036,1224 h35 r90
  text "B12" at 3340,1218 h35 r90
  text "B12" at 3385,1218 h35 r90
  text "MM32F103VxT6_CoreBoard V1.0" at 1500,1201 h60
  text "B13" at 2990,1122 h35 r90
  text "B13" at 3035,1122 h35 r90
  text "B10" at 3339,1121 h35 r90
  text "B10" at 3384,1121 h35 r90
  text "2018-5-15" at 1151,1089 h60
  text "E14" at 3339,1023 h35 r90
  text "E14" at 3384,1023 h35 r90
  text "B11" at 2990,1016 h35 r90
  text "B11" at 3035,1016 h35 r90
  text "E15" at 2990,921 h35 r90
  text "E15" at 3035,921 h35 r90
  text "E12" at 3339,921 h35 r90
  text "E12" at 3384,921 h35 r90
  text "E13" at 2990,817 h35 r90
  text "E13" at 3035,817 h35 r90
  text "E10" at 3339,816 h35 r90
  text "E10" at 3384,816 h35 r90
  text "E11" at 2990,713 h35 r90
  text "E11" at 3035,713 h35 r90
  text "E8" at 3339,708 h35 r90
  text "E8" at 3384,708 h35 r90
  text "LD-" at 3339,632 h35 r90
  text "GND" at 3384,632 h35 r90
  text "E9" at 2990,605 h35 r90
  text "E9" at 3035,605 h35 r90
  text "GND" at 3339,530 h35 r90
  text "GND" at 3384,530 h35 r90
  text "E7" at 2990,507 h35 r90
  text "E7" at 3035,507 h35 r90
  text "E2" at 478,295 h35
  text "E3" at 573,295 h35
  text "E4" at 679,295 h35
  text "E5" at 778,295 h35
  text "E6" at 877,295 h35
  text "C13" at 992,295 h35
  text "C14" at 1092,295 h35
  text "C15" at 1197,295 h35
  text "C0" at 1281,295 h35
  text "C1" at 1380,295 h35
  text "C2" at 1483,295 h35
  text "C3" at 1582,295 h35
  text "A0" at 1682,295 h35
  text "A1" at 1777,295 h35
  text "A2" at 1884,295 h35
  text "A4" at 2084,295 h35
  text "A5" at 2183,295 h35
  text "A6" at 2280,295 h35
  text "A7" at 2382,295 h35
  text "C4" at 2482,295 h35
  text "C5" at 2579,295 h35
  text "B0" at 2679,295 h35
  text "A3" at 1983,294 h35
  text "B1" at 2775,294 h35
  text "B2" at 2881,294 h35
  text "E2" at 478,250 h35
  text "E3" at 573,250 h35
  text "E4" at 679,250 h35
  text "E5" at 778,250 h35
  text "E6" at 877,250 h35
  text "C13" at 992,250 h35
  text "C14" at 1092,250 h35
  text "C15" at 1197,250 h35
  text "C0" at 1281,250 h35
  text "C1" at 1380,250 h35
  text "C2" at 1483,250 h35
  text "C3" at 1582,250 h35
  text "A0" at 1682,250 h35
  text "A1" at 1777,250 h35
  text "A2" at 1884,250 h35
  text "A4" at 2084,250 h35
  text "A5" at 2183,250 h35
  text "A6" at 2280,250 h35
  text "A7" at 2382,250 h35
  text "C4" at 2482,250 h35
  text "C5" at 2579,250 h35
  text "B0" at 2679,250 h35
  text "A3" at 1983,249 h35
  text "B1" at 2775,249 h35
  text "B2" at 2881,249 h35
Top Solder:
  rectangle: 539,959 665,1278
Mechanical 1:
  lines w5: 0,66 ccw(c66.03,65.55) 66,-0.48 ; 0.52,2098.5 cw(c66.55,2098.48) 67,2164.5 ; 3553.52,0 ccw(c3553.97,66.03) 3620,66 ; 3554,2164.5 cw(c3553.97,2098.48) 3620,2098.02 ; 0,2165 3620,2165 ; 0,2165 3620,2165 ; 0,2165 0,0 3620,0 3620,2165

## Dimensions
0,2165 to 0,0 on Mechanical 1
0,2165 to 3620,2165 on Mechanical 1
